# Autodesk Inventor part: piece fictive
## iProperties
Shininess: 64.0
Length Units: 11269
Angle Units: 11279
Time Units: 11290
Mass Units: 11283
Length Display Precision: 3
Angle Display Precision: 2
Compacted: True
Part Number: piece fictive
Document SubType Name: Modeling
Created: 2003-07
Material: Par défaut
Designer: robert
Density: 0.0
Volumn: 0.0
Area: 0.0
PropertySet Name: Model Information
Control State: 0
Master: False
Checked Out: False
Author: robert
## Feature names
1. Extrusion1
